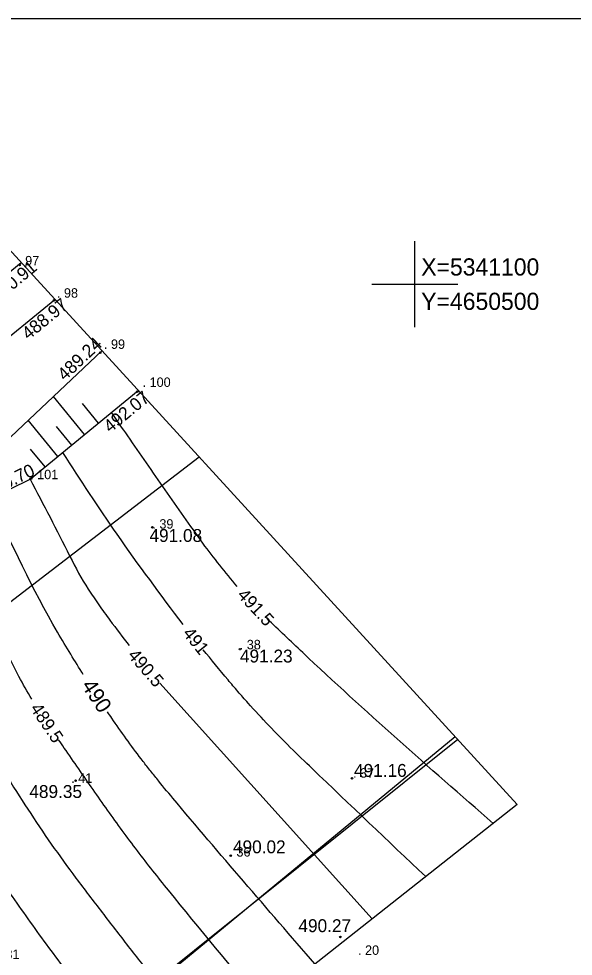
# Model space of a CAD drawing. Extents: x 4632591 to 4651113, y 5341001 to 5369868.
# Drawn here: x 4651046.64 to 4651067.44, y 5341056.78 to 5341091.9 of the extents above; entities that cross this region are included whole.
import ezdxf

# ---------------------------------------------------------------- set-up
doc = ezdxf.new("R2010")
doc.units = 0
doc.layers.add('Warstwa 1', color=7, linetype='Continuous')

msp = doc.modelspace()

# ---------------------------------------------------------------- linework, layer by layer
at = {"layer": 'Warstwa 1'}
for p, q in [((4651061.502, 5341080.347), (4651061.502, 5341083.566)), ((4651059.892, 5341081.956), (4651063.111, 5341081.956)), ((4651049.117, 5341076.325), (4651047.949, 5341077.749)), ((4651049.637, 5341076.751), (4651049.039, 5341077.481)), ((4651048.114, 5341075.502), (4651047.002, 5341076.858)), ((4651048.634, 5341075.929), (4651048.064, 5341076.624)), ((4651047.631, 5341075.106), (4651047.088, 5341075.767)), ((4651051.935, 5341067.009), (4651059.897, 5341058.173)), ((4651063.016, 5341064.991), (4651019.794, 5341029.436))]:
    msp.add_line(p, q, dxfattribs=at)
for points in [[(4650982.095, 5341091.899), (4650982.095, 5341000.802), (4651110.863, 5341000.802), (4651110.863, 5341091.899)], [(4651021.185, 5341027.659), (4650996.477, 5341059.231), (4651041.81, 5341088.134), (4651065.336, 5341062.46)]]:
    msp.add_lwpolyline(points, close=True, dxfattribs=at)
for points in [[(4651046.74, 5341082.754), (4651041.015, 5341078.074), (4651037.203, 5341075.808), (4651034.01, 5341073.477), (4651025.588, 5341069.279), (4651020.547, 5341067.161), (4651013.761, 5341062.963), (4651004.58, 5341057.838), (4651005.333, 5341056.171), (4651015.725, 5341060.98), (4651021.526, 5341064.56), (4651026.297, 5341067.167), (4651035.027, 5341070.084), (4651039.888, 5341071.127), (4651047.073, 5341074.649), (4651051.124, 5341077.97)], [(4651049.763, 5341079.455), (4651044.749, 5341074.739), (4651038.568, 5341072.193), (4651034.332, 5341071.623), (4651037.39, 5341074.726), (4651042.908, 5341077.237), (4651047.997, 5341081.382)], [(4651053.413, 5341075.471), (4651030.661, 5341058.033)], [(4651063.109, 5341064.89), (4651039.321, 5341045.863), (4651036.051, 5341043.262), (4651030.346, 5341038.542), (4651022.124, 5341032.065), (4651019.41, 5341029.927)]]:
    msp.add_lwpolyline(points, dxfattribs=at)
for centre in [(4651046.678, 5341082.676), (4651047.969, 5341081.348), (4651049.701, 5341079.389), (4651051.089, 5341077.928), (4651047.093, 5341074.664), (4651051.658, 5341072.848), (4651054.942, 5341068.279), (4651059.147, 5341063.444), (4651048.776, 5341063.35), (4651054.594, 5341060.547), (4651058.71, 5341057.499)]:
    msp.add_circle(centre, 0.029, dxfattribs=at)
for points in [[(4651054.833, 5341070.633), (4651053.553, 5341072.247), (4651052.84, 5341073.248), (4651052.133, 5341074.251), (4651050.733, 5341076.269), (4651050.125, 5341077.151)], [(4651052.807, 5341069.205), (4651050.335, 5341072.585), (4651048.296, 5341075.651)], [(4651047.073, 5341074.649), (4651048.551, 5341071.783), (4651048.565, 5341071.755), (4651049.252, 5341070.531), (4651049.448, 5341070.235), (4651049.648, 5341069.942), (4651050.064, 5341069.367), (4651050.785, 5341068.415)], [(4651049.067, 5341067.325), (4651048.596, 5341068.088), (4651048.104, 5341068.911), (4651045.581, 5341073.917)], [(4651047.135, 5341066.406), (4651046.651, 5341067.257), (4651046.168, 5341068.264), (4651046.063, 5341068.53), (4651045.967, 5341068.801), (4651045.87, 5341069.07), (4651045.758, 5341069.334), (4651043.972, 5341073.129)], [(4651064.436, 5341061.751), (4651057.294, 5341068.154), (4651055.957, 5341069.424)], [(4651061.91, 5341059.759), (4651057.654, 5341063.804), (4651056.831, 5341064.602), (4651056.028, 5341065.42), (4651055.247, 5341066.262), (4651054.867, 5341066.692), (4651054.494, 5341067.129), (4651053.565, 5341068.259)], [(4651057.756, 5341056.485), (4651052.42, 5341062.704), (4651051.819, 5341063.43), (4651051.526, 5341063.798), (4651051.236, 5341064.17), (4651050.135, 5341065.696), (4651049.974, 5341065.935)], [(4651055.809, 5341054.95), (4651052.264, 5341059.245), (4651051.094, 5341060.726), (4651049.978, 5341062.247), (4651048.893, 5341063.796), (4651048.354, 5341064.577), (4651048.139, 5341064.888)], [(4651045.974, 5341063.862), (4651046.133, 5341063.613), (4651046.987, 5341062.285), (4651047.866, 5341060.979), (4651048.792, 5341059.702), (4651049.769, 5341058.419), (4651050.754, 5341057.144), (4651051.759, 5341055.887), (4651052.796, 5341054.655), (4651053.949, 5341053.327)], [(4651044.065, 5341062.389), (4651044.851, 5341061.235), (4651045.646, 5341060.086), (4651046.99, 5341058.174), (4651048.372, 5341056.29), (4651049.082, 5341055.4), (4651049.818, 5341054.53), (4651050.554, 5341053.661), (4651051.263, 5341052.771), (4651051.928, 5341051.891)]]:
    msp.add_spline(points, degree=3, dxfattribs=at)

# ---------------------------------------------------------------- texts
for s, height, rotation, p in [('490.91', 0.4829, 39.7089, (4651045.853, 5341081.252)), ('488.97', 0.4829, 39.1609, (4651047.007, 5341079.846)), ('489.24', 0.4829, 43.2462, (4651048.372, 5341078.308)), ('492.07', 0.4829, 39.3465, (4651050.074, 5341076.364)), ('490.70', 0.4829, 26.1115, (4651045.521, 5341073.944)), ('491.5', 0.4829, 312.934, (4651054.811, 5341070.282)), ('491', 0.4829, 308.6958, (4651052.768, 5341068.864)), ('490.5', 0.4829, 310.8166, (4651050.706, 5341068.034)), ('490', 0.5795, 303.1621, (4651048.976, 5341066.92)), ('489.5', 0.4829, 303.7779, (4651047.053, 5341066.061))]:
    msp.add_text(s, height=height, rotation=rotation, dxfattribs=at).set_placement(p)
for s, height, p in [('. 97', 0.3541, (4651046.623, 5341082.658)), (' X=5341100 ', 0.64384, (4651061.502, 5341082.278)), ('. 98', 0.3541, (4651048.078, 5341081.448)), (' Y=4650500 ', 0.64384, (4651061.502, 5341080.991)), ('. 99', 0.3541, (4651049.842, 5341079.529)), ('. 100', 0.3541, (4651051.29, 5341078.106)), ('. 101', 0.3541, (4651047.073, 5341074.649)), ('. 39', 0.3541, (4651051.657, 5341072.795)), ('491.08', 0.4829, (4651051.549, 5341072.298)), ('. 38', 0.3541, (4651054.935, 5341068.275)), ('491.23', 0.4829, (4651054.942, 5341067.781)), ('. 37', 0.3541, (4651059.184, 5341063.465)), ('491.16', 0.4829, (4651059.22, 5341063.496)), ('. 41', 0.3541, (4651048.612, 5341063.272)), ('489.35', 0.4829, (4651047.043, 5341062.705)), ('490.02', 0.4829, (4651054.68, 5341060.633)), ('. 36', 0.3541, (4651054.548, 5341060.51)), ('490.27', 0.4829, (4651057.135, 5341057.679)), ('. 20', 0.3541, (4651059.371, 5341056.827)), ('. 31', 0.3541, (4651045.882, 5341056.673))]:
    msp.add_text(s, height=height, dxfattribs=at).set_placement(p)

doc.saveas('drawing.dxf')
